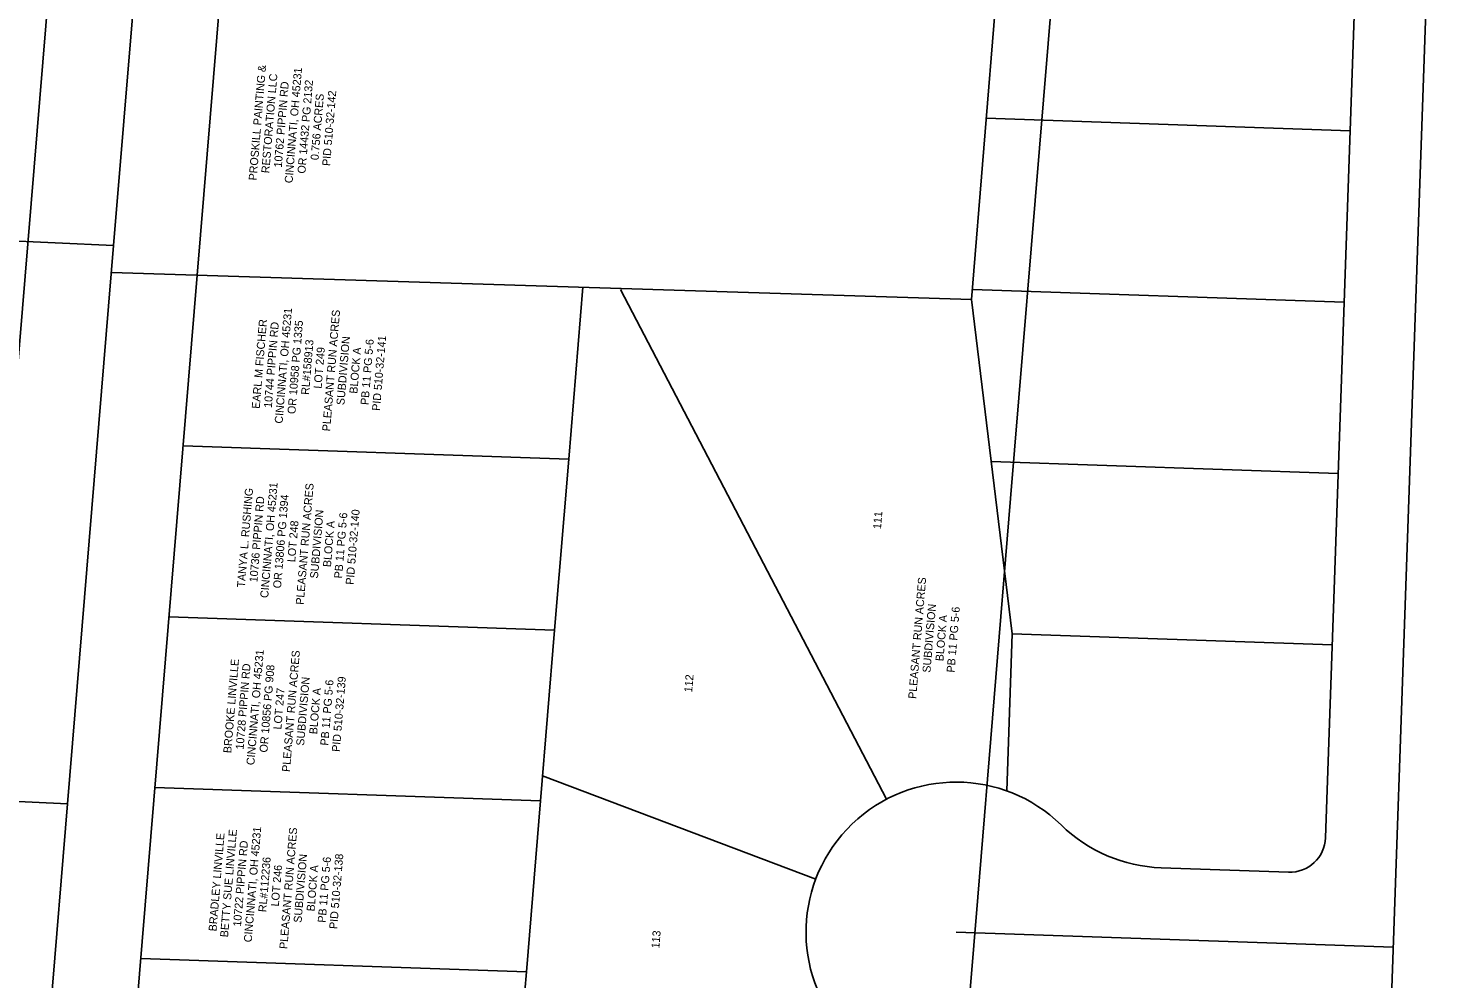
# Model space of a CAD drawing. Extents: x 1379776 to 1382941, y 467490 to 471592.
# Drawn here: x 1381550.8 to 1382042.2, y 469501.8 to 469834.6 of the extents above; entities that cross this region are included whole.
import ezdxf

# ---------------------------------------------------------------- set-up
doc = ezdxf.new("R2010")
doc.units = 0
for name, color, linetype in [('DR_X_Text', 7, 'Continuous'), ('PV_P_Drive', 7, 'Continuous'), ('PV_X_Driveway', 7, 'Continuous'), ('RC_X_Text', 7, 'Continuous'), ('RD_X_Wall', 7, 'Continuous'), ('SH_Named_Boundary', 7, 'Continuous'), ('SV_X_Break_Lines', 7, 'Continuous')]:
    doc.layers.add(name, color=color, linetype=linetype)

msp = doc.modelspace()

# ---------------------------------------------------------------- linework, layer by layer
at = {"layer": 'DR_X_Text'}
msp.add_line((1382028.36, 469512.91), (1381875.46, 469518.22), dxfattribs=at)
msp.add_lwpolyline([(1382016.8, 469180.11), (1382043.72, 469954.66), (1382306.88, 469945.51)], dxfattribs=at)
at = {"layer": 'PV_P_Drive'}
for p, q in [((1381622.42, 470262.79), (1381580.75, 469758.51)), ((1381880.85, 469739.58), (1381889.85, 469850.22)), ((1381096.92, 469780.54), (1381580.75, 469758.51)), ((1381580.75, 469758.51), (1381564.61, 469563.17)), ((1381579.97, 469749.09), (1381880.85, 469739.58)), ((1381744.91, 469743.88), (1381739.94, 469683.73)), ((1381739.94, 469683.73), (1381605.05, 469688.37)), ((1381739.94, 469683.73), (1381735, 469623.94)), ((1381600.11, 469628.57), (1381735, 469623.94)), ((1381735, 469623.94), (1381730.06, 469564.14)), ((1381080.78, 469585.21), (1381564.61, 469563.17)), ((1381730.06, 469564.14), (1381595.17, 469568.78)), ((1381564.61, 469563.17), (1381557.19, 469473.48)), ((1381730.06, 469564.14), (1381725.12, 469504.34)), ((1381590.23, 469508.98), (1381725.12, 469504.34)), ((1381725.12, 469504.34), (1381716.12, 469395.42))]:
    msp.add_line(p, q, dxfattribs=at)
at = {"layer": 'PV_X_Driveway'}
msp.add_line((1381609.99, 469748.14), (1381640.2, 470113.65), dxfattribs=at)
msp.add_lwpolyline([(1381481.91, 468926.74), (1381589.94, 470234.06), (1380557.84, 470275.29)], dxfattribs=at)
at = {"layer": 'RD_X_Wall'}
for p, q in [((1382017.11, 469908.92), (1382004.68, 469551.25)), ((1381563.78, 469188.96), (1381609.99, 469748.14)), ((1381991.75, 469539.19), (1381947.12, 469540.74))]:
    msp.add_line(p, q, dxfattribs=at)
for centre, radius, start, end in [((1381875.46, 469518.22), 52.5, 45.5788, 310.44), ((1381948.95, 469593.21), 52.5, 225.5788, 268.0094), ((1381992.19, 469551.69), 12.5, 268.0094, 358.0094)]:
    msp.add_arc(centre, radius, start, end, dxfattribs=at)
at = {"layer": 'SH_Named_Boundary'}
msp.add_lwpolyline([(1381019.66, 469039.84), (1381836.87, 468972.31), (1381848.4, 469111.83), (1381859.93, 469251.36), (1381871.46, 469390.88), (1381882.99, 469530.4), (1381894.52, 469669.93), (1381906.05, 469809.45), (1381917.58, 469948.98), (1381929.11, 470088.5), (1381940.64, 470228.03), (1381952.16, 470367.55), (1381134.95, 470435.08), (1381123.42, 470295.56), (1381111.89, 470156.03), (1381100.36, 470016.51), (1381088.83, 469876.98), (1381077.3, 469737.46), (1381065.77, 469597.93), (1381054.24, 469458.41), (1381042.71, 469318.88), (1381031.19, 469179.36)], close=True, dxfattribs=at)
at = {"layer": 'SV_X_Break_Lines'}
for p, q in [((1382013.28, 469798.6), (1381886.01, 469803.03)), ((1381758.01, 469743.08), (1381851.15, 469564.75)), ((1381895.09, 469622.6), (1381880.85, 469739.58)), ((1382011.19, 469738.64), (1381881.14, 469743.16)), ((1382009.11, 469678.67), (1381887.75, 469682.89)), ((1381895.09, 469622.6), (1381893.18, 469567.64)), ((1382007.03, 469618.71), (1381895.09, 469622.6)), ((1381730.78, 469572.87), (1381826.34, 469536.77))]:
    msp.add_line(p, q, dxfattribs=at)

# ---------------------------------------------------------------- texts
at = {"layer": 'RC_X_Text'}
for s, p in [('PROSKILL PAINTING &', (1381630.76, 469781.19)), ('RESTORATION LLC', (1381635.19, 469783.72)), ('CINCINNATI, OH 45231', (1381643.33, 469780.24)), ('10762 PIPPIN RD', (1381639.57, 469785.72)), ('OR 14432 PG 2132', (1381647.82, 469783.59)), ('PID 510-32-142', (1381656.47, 469786.26)), ('0.756 ACRES', (1381652.42, 469788.31)), ('CINCINNATI, OH 45231', (1381639.84, 469696.11)), ('PLEASANT RUN ACRES', (1381656.47, 469693.41)), ('EARL M FISCHER', (1381631.84, 469701.3)), ('10744 PIPPIN RD', (1381636.08, 469701.6)), ('OR 10958 PG 1335', (1381644.33, 469699.44)), ('RL#158913', (1381649.1, 469706.17)), ('SUBDIVISION', (1381661.45, 469702.58)), ('PB 11 PG 5-6', (1381669.88, 469702.62)), ('PID 510-32-141', (1381673.92, 469700.57)), ('LOT 249', (1381653.49, 469708.33)), ('BLOCK A', (1381665.99, 469706.58)), ('CINCINNATI, OH 45231', (1381634.8, 469635.06)), ('PLEASANT RUN ACRES', (1381647.24, 469632.71)), ('TANYA L. RUSHING', (1381626.67, 469638.73)), ('10736 PIPPIN RD', (1381631.03, 469640.55)), ('OR 13806 PG 1394', (1381639.29, 469638.45)), ('SUBDIVISION', (1381652.22, 469641.88)), ('PB 11 PG 5-6', (1381660.65, 469641.91)), ('PID 510-32-140', (1381664.68, 469639.7)), ('111', (1381849.16, 469659.17)), ('LOT 248', (1381644.26, 469647.6)), ('BLOCK A', (1381656.76, 469645.88)), ('PLEASANT RUN ACRES', (1381861.47, 469599.77)), ('SUBDIVISION', (1381866.45, 469608.94)), ('PB 11 PG 5-6', (1381874.88, 469608.97)), ('BLOCK A', (1381870.99, 469612.94)), ('CINCINNATI, OH 45231', (1381629.96, 469576.56)), ('PLEASANT RUN ACRES', (1381642.41, 469574.2)), ('BROOKE LINVILLE', (1381621.88, 469580.76)), ('10728 PIPPIN RD', (1381626.2, 469582.04)), ('OR 10856 PG 908', (1381634.54, 469580.99)), ('SUBDIVISION', (1381647.38, 469583.38)), ('PB 11 PG 5-6', (1381655.81, 469583.41)), ('PID 510-32-139', (1381659.85, 469581.22)), ('112', (1381783.11, 469602.04)), ('LOT 247', (1381639.42, 469589.04)), ('BLOCK A', (1381651.93, 469587.38)), ('BRADLEY LINVILLE', (1381616.73, 469518.41)), ('BETTY SUE LINVILLE', (1381620.77, 469516.33)), ('CINCINNATI, OH 45231', (1381629.05, 469514.58)), ('PLEASANT RUN ACRES', (1381641.5, 469512.22)), ('10722 PIPPIN RD', (1381625.29, 469520.06)), ('RL#112236', (1381634.14, 469525.11)), ('SUBDIVISION', (1381646.47, 469521.4)), ('PB 11 PG 5-6', (1381654.91, 469521.43)), ('PID 510-32-138', (1381658.94, 469519.21)), ('LOT 246', (1381638.52, 469527.11)), ('BLOCK A', (1381651.02, 469525.4)), ('113', (1381771.62, 469512.43))]:
    msp.add_text(s, height=2.8, rotation=85.2762, dxfattribs=at).set_placement(p)

doc.saveas('drawing.dxf')
